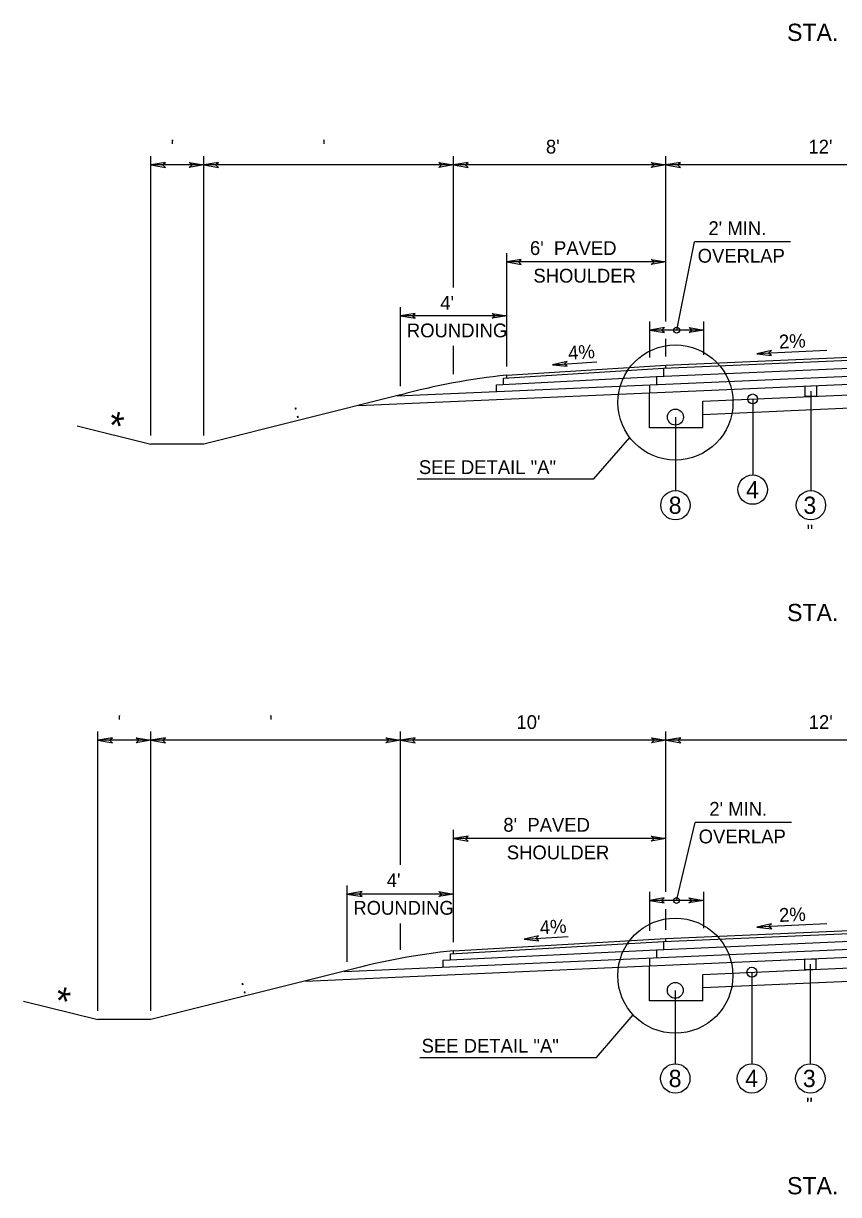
# Model space of a CAD drawing. Extents: x -592 to 1199, y -590 to 416.
# Drawn here: x 144.6 to 227.3, y 43.7 to 162.5 of the extents above; entities that cross this region are included whole.
import ezdxf

# ---------------------------------------------------------------- set-up
doc = ezdxf.new("R2010")
doc.units = 0
doc.layers.add('1', color=7, linetype='Continuous')
doc.layers.add('Des_ Drain_ Ftrs', color=7, linetype='Continuous')

msp = doc.modelspace()

# ---------------------------------------------------------------- linework, layer by layer
at = {"layer": '1'}
for p, q in [((157.49, 120.71), (157.49, 149.04)), ((162.88, 120.71), (162.88, 149.04)), ((188.21, 135.73), (188.21, 149.04)), ((209.76, 132.28), (209.76, 149.04)), ((162.88, 148.16), (157.49, 148.16)), ((188.21, 148.16), (162.88, 148.16)), ((209.76, 148.16), (188.21, 148.16)), ((242.09, 148.16), (209.76, 148.16)), ((210.86, 131.4), (212.66, 140.34)), ((222.42, 140.34), (212.66, 140.34)), ((193.61, 127.71), (193.61, 139.2)), ((209.76, 138.32), (193.61, 138.32)), ((182.83, 125.7), (182.83, 133.74)), ((193.61, 132.86), (182.83, 132.86)), ((208.12, 128.62), (208.12, 132.28)), ((213.6, 128.89), (213.6, 132.28)), ((213.6, 131.4), (208.12, 131.4)), ((188.21, 126.93), (188.21, 129.79)), ((209.76, 128.72), (209.76, 130.52)), ((209.52, 127.53), (242.09, 128.95)), ((209.76, 127.84), (242.09, 129.25)), ((226.08, 129.32), (219, 129.01)), ((182.49, 124.73), (242.09, 127.33)), ((193.3, 126.51), (209.52, 127.53)), ((193.61, 126.83), (209.76, 127.84)), ((198.26, 127.89), (202.75, 128.17)), ((208.82, 126.69), (242.09, 128.14)), ((209.52, 127.52), (209.52, 126.71)), ((209.76, 127.54), (209.76, 127.84)), ((192.57, 125.86), (208.82, 126.68)), ((193.3, 125.89), (193.3, 126.51)), ((193.61, 126.53), (193.61, 126.83)), ((208.82, 126.67), (208.82, 125.89)), ((213.6, 125.28), (242.09, 126.53)), ((182.83, 124.82), (162.88, 119.83)), ((178.57, 123.75), (208.11, 125.04)), ((192.57, 125.17), (192.57, 125.86)), ((208.11, 125.86), (208.11, 125.04)), ((208.11, 125.04), (213.6, 125.28)), ((208.11, 121.5), (208.11, 125.04)), ((213.5, 124.2), (242.09, 125.45)), ((224.48, 125.22), (224.48, 115.12)), ((213.5, 121.5), (213.5, 124.2)), ((213.5, 122.85), (242.09, 124.1)), ((218.57, 124.42), (218.57, 116.7)), ((210.73, 122.58), (210.73, 115.12)), ((150.02, 121.7), (157.49, 119.83)), ((213.5, 121.5), (208.11, 121.5)), ((202.45, 116.3), (206.1, 120.51)), ((162.88, 119.83), (157.49, 119.83)), ((184.52, 116.3), (202.45, 116.3)), ((152.11, 62.34), (152.11, 90.67)), ((157.5, 62.34), (157.5, 90.67)), ((182.82, 77.17), (182.82, 90.67)), ((209.76, 74.43), (209.76, 90.67)), ((157.5, 89.79), (152.11, 89.79)), ((182.84, 89.79), (157.5, 89.79)), ((209.78, 89.79), (182.84, 89.79)), ((242.11, 89.79), (209.78, 89.79)), ((210.88, 73.66), (212.75, 81.44)), ((222.51, 81.44), (212.75, 81.44)), ((188.22, 69.32), (188.22, 80.7)), ((209.76, 79.82), (188.22, 79.82)), ((177.44, 67.32), (177.44, 75.08)), ((188.22, 74.2), (177.44, 74.2)), ((208.12, 70.48), (208.12, 74.43)), ((213.6, 70.74), (213.6, 74.43)), ((213.58, 73.55), (208.09, 73.55)), ((209.76, 70.58), (209.76, 72.67)), ((182.82, 68.55), (182.82, 71.22)), ((209.52, 69.39), (242.09, 70.81)), ((209.75, 69.7), (242.09, 71.11)), ((226.09, 71.16), (219, 70.85)), ((177.11, 66.35), (242.09, 69.19)), ((187.91, 68.13), (209.52, 69.39)), ((188.22, 68.44), (209.75, 69.7)), ((195.37, 69.62), (199.86, 69.88)), ((208.81, 68.55), (242.09, 70)), ((209.52, 69.39), (209.52, 68.58)), ((209.75, 69.4), (209.75, 69.7)), ((187.18, 67.48), (208.81, 68.55)), ((187.91, 67.51), (187.91, 68.13)), ((188.22, 68.14), (188.22, 68.44)), ((208.81, 68.55), (208.81, 67.74)), ((213.6, 67.14), (242.09, 68.38)), ((173.18, 65.37), (208.11, 66.9)), ((187.18, 66.79), (187.18, 67.48)), ((208.11, 67.71), (208.11, 66.9)), ((208.11, 66.9), (213.6, 67.14)), ((208.11, 63.36), (208.11, 66.9)), ((213.5, 66.05), (242.09, 67.3)), ((224.42, 67.07), (224.42, 56.98)), ((177.44, 66.44), (157.5, 61.46)), ((213.5, 63.36), (213.5, 66.05)), ((213.5, 64.71), (242.09, 65.95)), ((218.49, 66.27), (218.49, 56.98)), ((210.72, 64.43), (210.72, 56.98)), ((144.57, 63.34), (152.11, 61.46)), ((213.5, 63.36), (208.11, 63.36)), ((202.72, 57.61), (206.46, 61.93)), ((157.5, 61.46), (152.11, 61.46)), ((184.79, 57.61), (202.72, 57.61))]:
    msp.add_line(p, q, dxfattribs=at)
for points in [[(223.9, 125.73), (225.05, 125.78), (225.05, 124.7), (223.9, 124.65)], [(223.85, 67.58), (224.99, 67.63), (224.99, 66.56), (223.85, 66.51)]]:
    msp.add_lwpolyline(points, close=True, dxfattribs=at)
for centre, radius in [((210.86, 131.4), 0.3), ((210.73, 124.06), 5.84), ((218.57, 124.42), 0.5), ((210.73, 122.58), 0.808), ((218.57, 115.22), 1.49), ((210.73, 113.64), 1.49), ((224.48, 113.64), 1.49), ((210.84, 73.55), 0.3), ((210.72, 65.92), 5.84), ((218.49, 66.27), 0.5), ((210.72, 64.43), 0.808), ((210.72, 55.49), 1.49), ((218.49, 55.49), 1.49), ((224.42, 55.49), 1.49)]:
    msp.add_circle(centre, radius, dxfattribs=at)
for centre, end in [((200.49, 59.99), 105.2395), ((195.1, 1.61), 105.2381)]:
    msp.add_arc(centre, 67.19, 95.8795, end, dxfattribs=at)
at = {"layer": 'Des_ Drain_ Ftrs'}
for points in [[(157.49, 148.16), (158.98, 147.91), (158.69, 148.16), (158.98, 148.41)], [(162.88, 148.16), (161.39, 147.91), (161.69, 148.16), (161.39, 148.41)], [(162.88, 148.16), (164.37, 147.91), (164.08, 148.16), (164.37, 148.41)], [(188.21, 148.16), (186.72, 147.91), (187.01, 148.16), (186.72, 148.41)], [(188.21, 148.16), (189.7, 147.91), (189.4, 148.16), (189.7, 148.41)], [(209.76, 148.16), (208.27, 147.91), (208.57, 148.16), (208.27, 148.41)], [(209.76, 148.16), (211.25, 147.91), (210.95, 148.16), (211.25, 148.41)], [(193.61, 138.32), (195.09, 138.07), (194.8, 138.32), (195.09, 138.56)], [(209.76, 138.32), (208.27, 138.07), (208.57, 138.32), (208.27, 138.56)], [(182.83, 132.86), (184.32, 132.61), (184.02, 132.86), (184.32, 133.1)], [(193.61, 132.86), (192.12, 132.61), (192.41, 132.86), (192.12, 133.1)], [(208.12, 131.4), (209.61, 131.15), (209.31, 131.4), (209.61, 131.65)], [(213.6, 131.4), (212.12, 131.15), (212.41, 131.4), (212.12, 131.65)], [(219, 129.01), (220.49, 128.83), (220.19, 129.06), (220.47, 129.32)], [(198.26, 127.89), (199.76, 127.73), (199.45, 127.96), (199.73, 128.23)], [(152.11, 89.79), (153.6, 89.54), (153.3, 89.79), (153.6, 90.04)], [(157.5, 89.79), (156.01, 89.54), (156.3, 89.79), (156.01, 90.04)], [(157.5, 89.79), (158.98, 89.54), (158.69, 89.79), (158.98, 90.04)], [(182.84, 89.79), (181.35, 89.54), (181.65, 89.79), (181.35, 90.04)], [(182.84, 89.79), (184.33, 89.54), (184.04, 89.79), (184.33, 90.04)], [(209.78, 89.79), (208.3, 89.54), (208.59, 89.79), (208.3, 90.04)], [(209.78, 89.79), (211.27, 89.54), (210.98, 89.79), (211.27, 90.04)], [(188.22, 79.82), (189.7, 79.57), (189.41, 79.82), (189.7, 80.07)], [(209.76, 79.82), (208.27, 79.57), (208.56, 79.82), (208.27, 80.07)], [(177.44, 74.2), (178.93, 73.95), (178.63, 74.2), (178.93, 74.45)], [(188.22, 74.2), (186.73, 73.95), (187.02, 74.2), (186.73, 74.45)], [(208.09, 73.55), (209.58, 73.3), (209.29, 73.55), (209.58, 73.8)], [(213.58, 73.55), (212.09, 73.3), (212.39, 73.55), (212.09, 73.8)], [(219, 70.85), (220.5, 70.67), (220.19, 70.9), (220.48, 71.16)], [(195.37, 69.62), (196.87, 69.46), (196.57, 69.69), (196.85, 69.95)]]:
    msp.add_lwpolyline(points, close=True, dxfattribs=at)

# ---------------------------------------------------------------- texts
at = {"layer": '1'}
for s, height, p in [('STA.    +      TO STA.    +     ', 1.75, (222.06, 160.73)), (" '", 1.4, (158.99, 149.31)), ("  '", 1.4, (173.85, 149.31)), ("8'", 1.4, (197.59, 149.31)), ("12'", 1.4, (224.23, 149.31)), ("2' MIN.", 1.4, (214.08, 141.04)), ("6'  PAVED", 1.4, (195.97, 139.02)), ('OVERLAP', 1.4, (212.99, 138.24)), ('SHOULDER', 1.4, (196.32, 136.22)), ("4'", 1.4, (186.87, 133.47)), ('ROUNDING', 1.4, (183.48, 130.67)), ('SEE DETAIL "A"', 1.4, (184.7, 116.8)), ('4', 1.75, (217.9, 114.34)), ('8', 1.75, (210.05, 112.76)), ('3', 1.75, (223.72, 112.76)), (' "', 1.4, (223.53, 110.28)), ('STA.    +      TO STA.    +     ', 1.75, (222.06, 101.88)), (" '", 1.4, (153.61, 90.94)), ("  '", 1.4, (168.47, 90.94)), ("10'", 1.4, (194.6, 90.94)), ("12'", 1.4, (224.26, 90.94)), ("2' MIN.", 1.4, (214.17, 82.14)), ("8'  PAVED", 1.4, (193.27, 80.52)), ('OVERLAP', 1.4, (213.09, 79.34)), ('SHOULDER', 1.4, (193.62, 77.72)), ("4'", 1.4, (181.44, 74.9)), ('ROUNDING', 1.4, (178.05, 72.1)), ('SEE DETAIL "A"', 1.4, (184.98, 58.11)), ('8', 1.75, (210.05, 54.62)), ('4', 1.75, (217.81, 54.62)), ('3', 1.75, (223.66, 54.62)), (' "', 1.4, (223.48, 52.13)), ('STA.    +      TO STA.    +     ', 1.75, (222.06, 43.74))]:
    msp.add_text(s, height=height, dxfattribs=at).set_placement(p)
for s, height, rotation, p in [('2%', 1.4, 2.6268, (221.27, 129.52)), ('4%', 1.4, 3.8754, (199.89, 128.38)), (' : ', 1.4, 14.2282, (171.68, 122.31)), ('*', 2.8, 347.1521, (152.93, 120.52)), ('2%', 1.4, 2.627, (221.28, 71.36)), ('4%', 1.4, 3.6082, (197.01, 70.1)), ('*', 2.8, 347.1521, (147.51, 62.15)), (' : ', 1.4, 14.2282, (166.29, 63.93))]:
    msp.add_text(s, height=height, rotation=rotation, dxfattribs=at).set_placement(p)

doc.saveas('drawing.dxf')
